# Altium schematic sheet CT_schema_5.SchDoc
size 578 x 363 mm
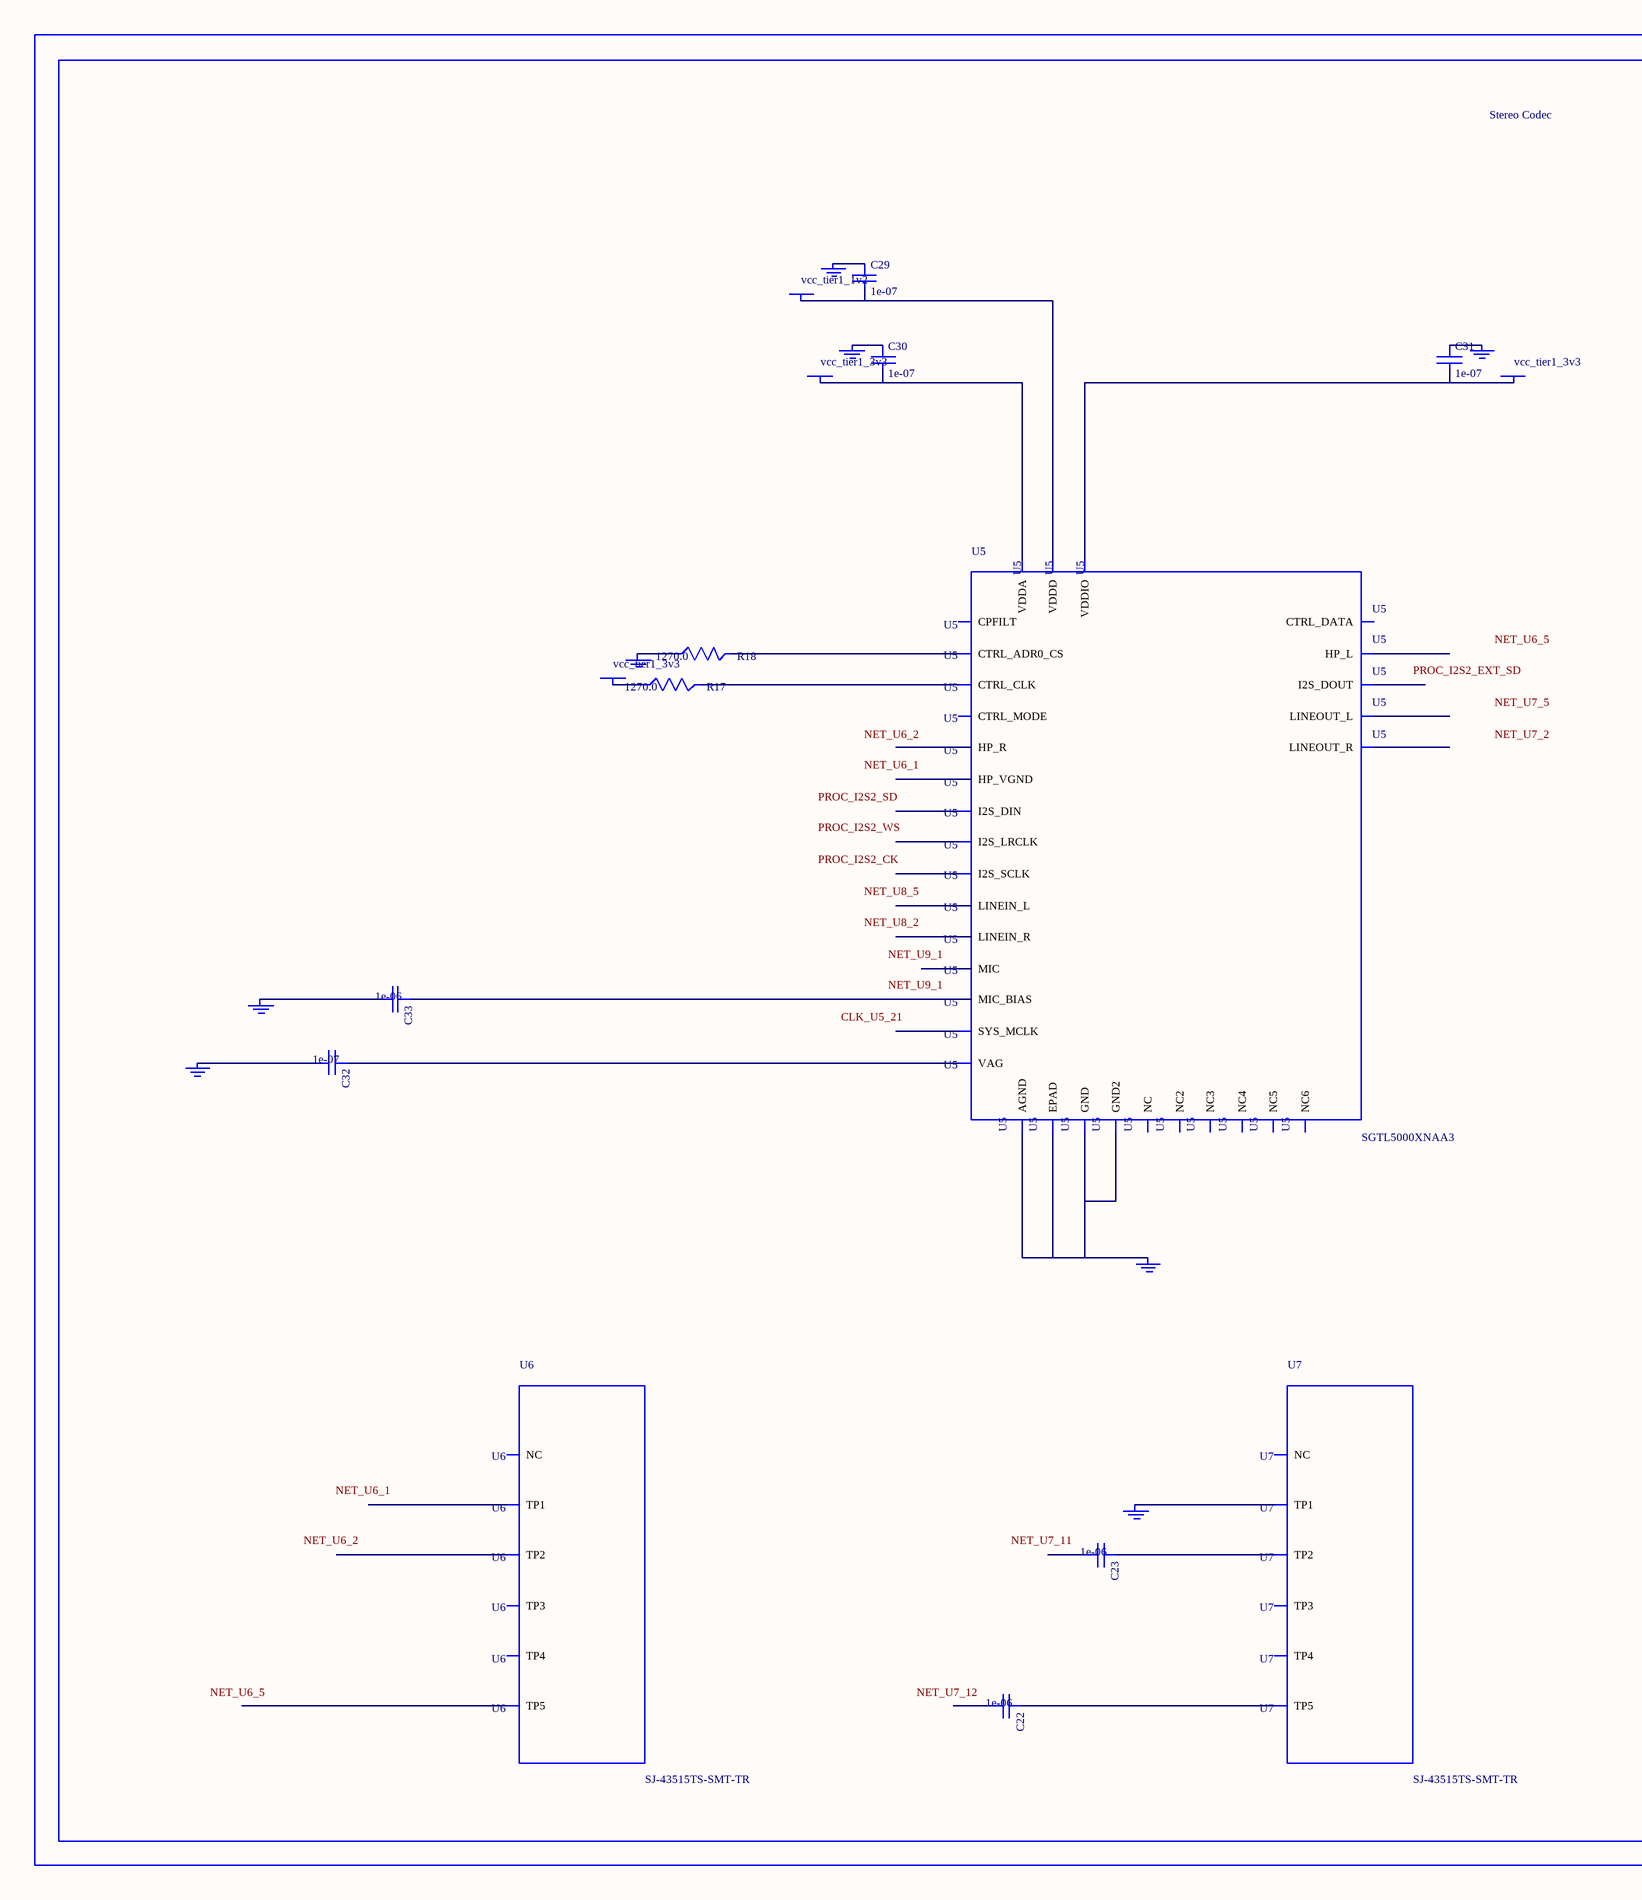
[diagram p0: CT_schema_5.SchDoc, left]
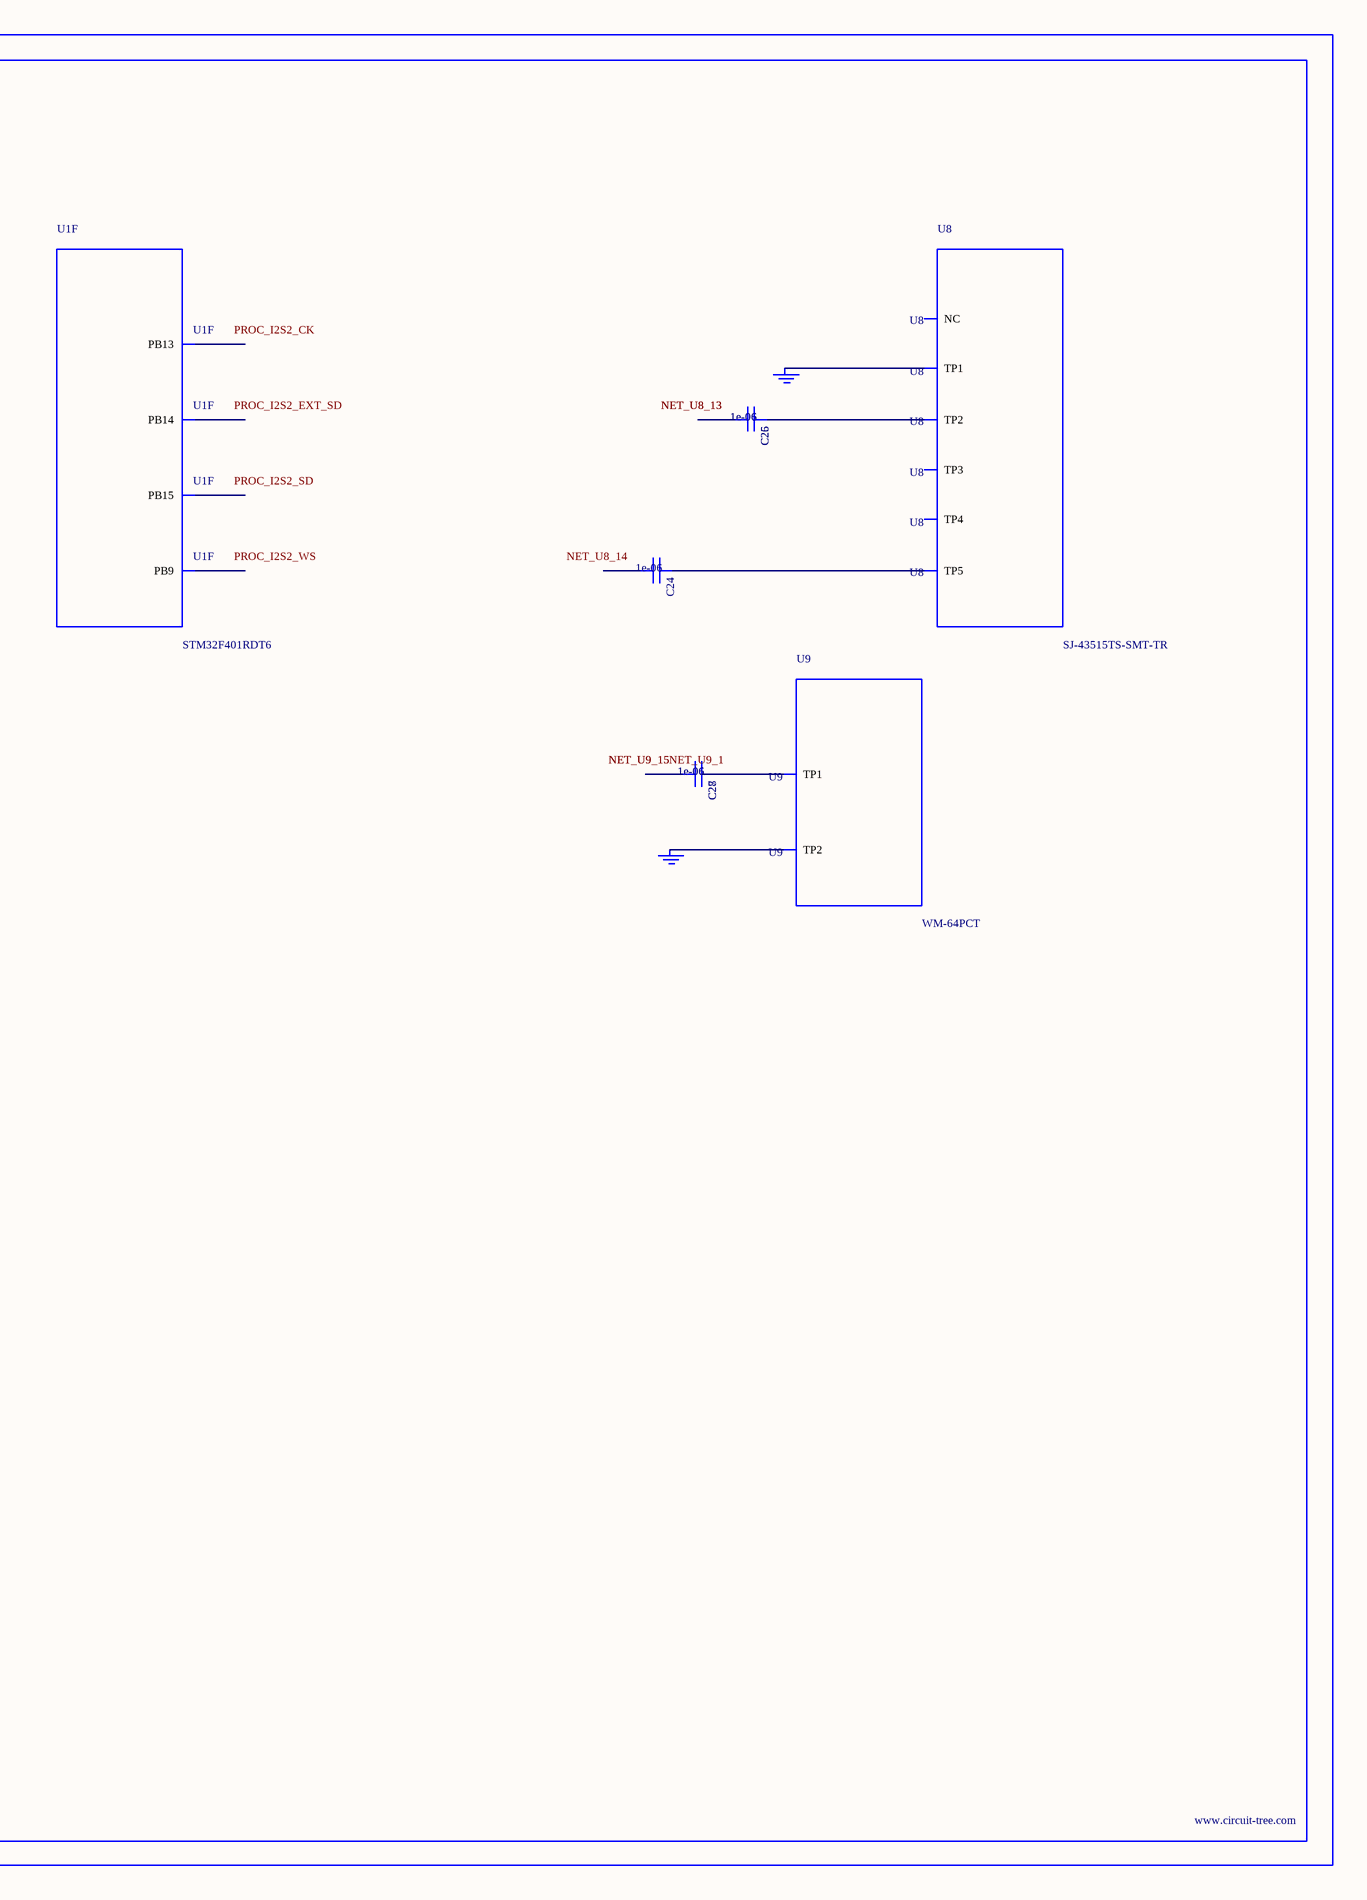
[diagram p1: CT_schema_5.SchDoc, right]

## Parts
BORDER4  (no value)
C22  1e-06  [C0603]
C23  1e-06  [C0603]
C24  1e-06  [C0603]
C25  1e-06  [C0603]
C26  1e-06  [C0603]
C27  1e-06  [C0603]
C28  1e-06  [C0603]
C29  1e-07  [C0402]
C30  1e-07  [C0402]
C31  1e-07  [C0402]
C32  1e-07  [C0402]
C33  1e-06  [C0603]
GND_INSTANCE_4_0  (no value)
GND_INSTANCE_4_1  (no value)
GND_INSTANCE_4_2  (no value)
GND_INSTANCE_4_3  (no value)
GND_INSTANCE_4_4  (no value)
GND_INSTANCE_4_5  (no value)
GND_INSTANCE_4_6  (no value)
GND_INSTANCE_4_7  (no value)
GND_INSTANCE_4_8  (no value)
GND_INSTANCE_4_9  (no value)
GND_INSTANCE_4_10  (no value)
POWER_INSTANCE_4_0  vcc_tier1_3v3
POWER_INSTANCE_4_1  vcc_tier1_3v3
POWER_INSTANCE_4_2  vcc_tier1_3v3
POWER_INSTANCE_4_3  vcc_tier1_1v2
R17  1270.0  [R0603]
R18  1270.0  [R0603]
U1  STM32F401RDT6  [LQFP64]  (part F of 7)
U5  SGTL5000XNAA3  [QFN-32]
U6  SJ-43515TS-SMT-TR  [SJ-43515TS-SMT-TR]
U7  SJ-43515TS-SMT-TR  [SJ-43515TS-SMT-TR]
U8  SJ-43515TS-SMT-TR  [SJ-43515TS-SMT-TR]
U9  WM-64PCT  [WM-64PC]

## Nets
NetC22_1: C22.1 U7.5(TP5)
NetC23_1: C23.1 U7.2(TP2)
NetC24_1: C24.1 U8.5(TP5)
NetC25_1: C25.1 C26.1 U8.2(TP2)
NetC25_2: C25.2 C26.2
NetC27_1: C27.1 C28.1 U9.1(TP1)
NetC27_2: C27.2 C28.2
NetC29_1: C29.1 GND_INSTANCE_4_5.0(GND)
NetC29_2: C29.2 POWER_INSTANCE_4_3.0(PWR) U5.30(VDDD)
NetC30_1: C30.1 GND_INSTANCE_4_1.0(GND)
NetC30_2: C30.2 POWER_INSTANCE_4_0.0(PWR) U5.5(VDDA)
NetC31_1: C31.1 GND_INSTANCE_4_4.0(GND)
NetC31_2: C31.2 POWER_INSTANCE_4_1.0(PWR) U5.20(VDDIO)
NetC32_1: C32.1 U5.10(VAG)
NetC32_2: C32.2 GND_INSTANCE_4_2.0(GND)
NetC33_1: C33.1 U5.16(MIC_BIAS)
NetC33_2: C33.2 GND_INSTANCE_4_3.0(GND)
NetGND_INSTANCE_4_0_0: GND_INSTANCE_4_0.0(GND) U5.1(GND) U5.3(GND2) U5.7(AGND) U5.EXP(EPAD)
NetGND_INSTANCE_4_6_0: GND_INSTANCE_4_6.0(GND) R18.1
NetGND_INSTANCE_4_7_0: GND_INSTANCE_4_7.0(GND) U7.1(TP1)
NetGND_INSTANCE_4_8_0: GND_INSTANCE_4_8.0(GND) GND_INSTANCE_4_9.0(GND) U8.1(TP1)
NetGND_INSTANCE_4_10_0: GND_INSTANCE_4_10.0(GND) U9.2(TP2)
NetPOWER_INSTANCE_4_2_0: POWER_INSTANCE_4_2.0(PWR) R17.1
NetR17_2: R17.2 U5.29(CTRL_CLK)
NetR18_2: R18.2 U5.31(CTRL_ADR0_CS)

Not connected (* = marked no-connect by the designer): C22 2; C23 2; C24 2; U1 34(PB13) 35(PB14) 36(PB15) 62(PB9); U5 2(HP_R) 4(HP_VGND) 6(HP_L) 8(NC) 9(NC2) 11(LINEOUT_R) 12(LINEOUT_L) 13(LINEIN_R) 14(LINEIN_L) 15(MIC) 17(NC3) 18(CPFILT) 19(NC4) 21(SYS_MCLK) 22(NC5) 23(I2S_LRCLK) 24(I2S_SCLK) 25(I2S_DOUT) 26(I2S_DIN) 27(CTRL_DATA) 28(NC6) 32(CTRL_MODE); U6 1(TP1) 2(TP2) 3(TP3) 4(TP4) 5(TP5) 6(NC); U7 3(TP3) 4(TP4) 6(NC); U8 3(TP3) 4(TP4) 6(NC)

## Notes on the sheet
- Labels drawn without touching a wire or pin: CLK_U5_21, NET_U6_1, NET_U6_2, NET_U6_5, NET_U7_2, NET_U7_5, NET_U7_11, NET_U7_12, NET_U8_2, NET_U8_5, NET_U8_14, NET_U9_1, PROC_I2S2_CK, PROC_I2S2_EXT_SD, PROC_I2S2_SD, PROC_I2S2_WS

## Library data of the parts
BORDER4 = BORDER_PAGE4
C22-C28 C33 = C0603C105K3RACTU
C29-C32 = C0402C104K3RACTU
GND_INSTANCE_4_0-GND_INSTANCE_4_10 = GND
POWER_INSTANCE_4_0-POWER_INSTANCE_4_3 = PWR
R17 R18 = RC0603FR-071K27L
